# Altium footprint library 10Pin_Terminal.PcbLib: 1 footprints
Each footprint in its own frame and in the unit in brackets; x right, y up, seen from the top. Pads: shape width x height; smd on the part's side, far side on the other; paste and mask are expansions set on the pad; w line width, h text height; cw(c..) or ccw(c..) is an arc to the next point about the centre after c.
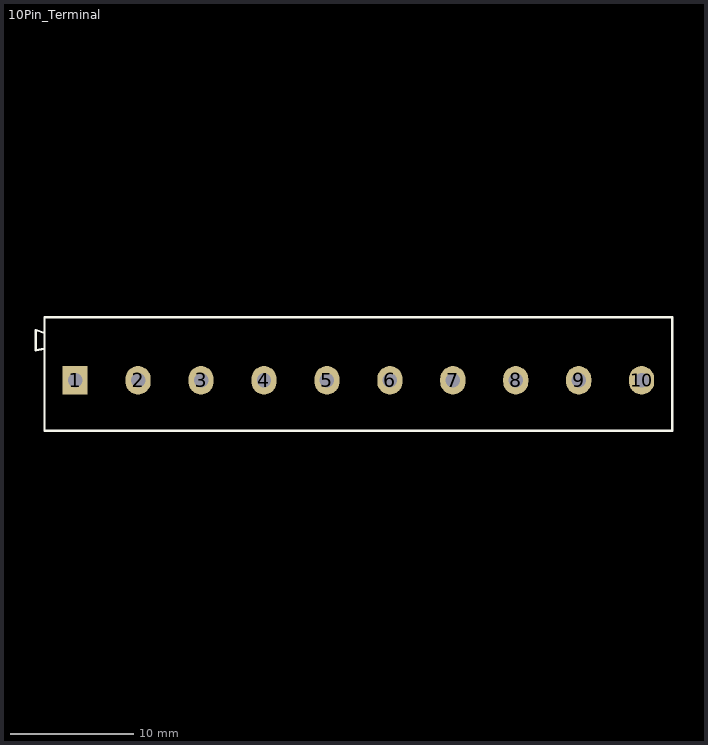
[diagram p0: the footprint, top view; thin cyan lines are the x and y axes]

## 10Pin_Terminal [mil]
pads (10):
  rect 80x90 hole 46: 1(3683.7,2208.15)
  oval 80x90 hole 46: 2(3883.7,2208.15) 3(4083.7,2208.15) 4(4283.7,2208.15) 5(4483.7,2208.15) 6(4683.7,2208.15) 7(4883.7,2208.15) 8(5083.7,2208.15) 9(5283.7,2208.15) 10(5483.7,2208.15)
Top Overlay:
  lines w7: 3586.7,2308.15 3558.7,2303.48 3558.7,2367.48 3586.7,2358.15 ; 3586.7,2048.15 5580.7,2048.15 5580.7,2408.15 3586.7,2408.15 3586.7,2048.15
3D body "Socket Blue_10Pin.STEP": height 493, standoff -263.18, extent 3556.7,2047.65 5579.7,2404.65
